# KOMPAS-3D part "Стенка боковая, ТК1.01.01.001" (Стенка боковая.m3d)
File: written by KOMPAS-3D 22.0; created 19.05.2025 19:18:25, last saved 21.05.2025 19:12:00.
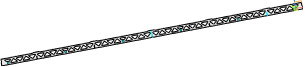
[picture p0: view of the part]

Document properties: Автор: user; Полное имя файла: КД\Стенка боковая.cdw

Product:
- Part/product: Стенка боковая  | designation ТК1.01.01.001
    Масса: 11.51708
- Part/product: Стенка боковая  | designation ТК1.01.01.001-01
    Масса: 11.528421
    source file: Раскрои\01 - Стенка боковая.cdw

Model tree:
1. Эскиз:1
2. Элемент выдавливания:1
     Расстояние 1 = 5
3. Эскиз:2  (with: Элемент выдавливания:1)
4. Эскиз:3  (with: Элемент выдавливания:1)
5. Элемент выдавливания:2
     Расстояние 2 = 5
6. Массив по сетке:1  (with: Элемент выдавливания:2, Элемент выдавливания:1)  (6 pattern instances)
     Угол раствора = 90
7. Эскиз:4  (with: Элемент выдавливания:1)
8. Элемент выдавливания:3  (with: Элемент выдавливания:1)
     Расстояние 2 = 5
9. Скругление:1  (with: Элемент выдавливания:3)
     Радиус = 5
10. Массив по сетке:2  (with: Элемент выдавливания:3, Эскиз:4, Скругление:1, Элемент выдавливания:1)  (6 pattern instances)
     Угол раствора = 90
11. Эскиз:5  (with: Элемент выдавливания:1, Элемент выдавливания:3)
12. Элемент выдавливания:4
     Расстояние 2 = 10
13. Скругление:2  (with: Элемент выдавливания:4)
     Радиус = 5
14. Массив по сетке:3  (with: Элемент выдавливания:4, Эскиз:5, Скругление:2, Элемент выдавливания:1)  (4 pattern instances)
     Угол раствора = 90
15. Эскиз:6  (with: Элемент выдавливания:1, Элемент выдавливания:3)
16. Элемент выдавливания:5
     Расстояние 2 = 5
17. Скругление:3  (with: Элемент выдавливания:5)
     Радиус = 5
18. Массив по сетке:4  (with: Элемент выдавливания:5, Эскиз:6, Скругление:3, Элемент выдавливания:1)  (labels: v390_v248)  (4 pattern instances)
     Угол раствора = 90
19. Эскиз:7  (with: Элемент выдавливания:1, Элемент выдавливания:4)
20. Элемент выдавливания:6
     Расстояние 2 = 5
21. Скругление:4  (with: Элемент выдавливания:6)
     Радиус = 5
22. Нормальная плоскость:1  (with: Элемент выдавливания:2)
     Угол = 90
23. Средняя плоскость:1
24. Массив по сетке:6  (with: Элемент выдавливания:6, Эскиз:7, Скругление:4, Элемент выдавливания:4, Эскиз:5, Скругление:2)  (labels: v490_v248)  (2 pattern instances)
     Шаг 1 = 184.8; Угол раствора = 90
25. Зеркальный массив:2
26. Экземпляр ( 1 )
27. Экземпляр ( 2 )  (with: Массив по сетке:6, Экземпляр ( 1 ), Элемент выдавливания:6, Скругление:4, Элемент выдавливания:4, Скругление:2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)  (2 pattern instances)
28. Линейный размер:2  (with: Элемент выдавливания:1)
     Значение = 100
29. Эскиз:8  (with: Элемент выдавливания:1)
30. Эскиз:9  (with: Элемент выдавливания:1)
31. Элемент выдавливания:7
     Расстояние 2 = 10
32. Эскиз:10  (with: Элемент выдавливания:1)
33. Элемент выдавливания:8
     Расстояние 2 = 10
34. Средняя плоскость:2  (with: Элемент выдавливания:1)
35. Зеркальный массив:3  (with: Экземпляр ( 1 ), Экземпляр ( 2 ), Элемент выдавливания:8)
36. Массив по сетке:7  (with: Элемент выдавливания:7, Эскиз:9, Зеркальный массив:2, Массив по сетке:6, Элемент выдавливания:6, Скругление:4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)  (29 pattern instances)
     Угол раствора = 90
37. Эскиз:11  (with: Элемент выдавливания:1, Элемент выдавливания:8, Элемент выдавливания:7)
38. Элемент выдавливания:9  (labels: v390_v248; v490_v248; v1116_v1114)
     Расстояние 2 = 5
39. Эскиз:13  (with: Элемент выдавливания:1)
40. Элемент выдавливания:11  (with: Элемент выдавливания:1)
     Расстояние 2 = 5

Expressions: (Lm-2*Hfte)/5; H/2+0.6; (Lm-2*Hfte)/10+Hfte
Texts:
  ТК1.01.01.001
  ТК1.01.01.001-01
  ТК1.01.01.001|Lm
  ТК1.01.01.001|Hfte
  ТК1.01.01.001|H
  ТК1.01.01.001|s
